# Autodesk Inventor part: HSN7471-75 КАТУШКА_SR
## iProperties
Created: 2011-02
Part Number: HSN7471-75 КАТУШКА_SR
Document SubType Name: Modeling
Designer: Чернышев Юрий
Mass: 173.104 g
Surface Area: 240.528 cm^2
Volume: 173.104 cm^3
Density: 1 g/cm^3
Author: Чернышев Юрий
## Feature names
1. ExtrusionBlind1
2. ExtrusionBlind2
3. Fillet1
4. Hole1
5. ExtrusionBlind3
6. ExtrusionBlind4
7. Fillet2
8. Fillet3
9. Fillet4
10. Fillet5
11. ExtrusionBlind5
12. ExtrusionBlind6
